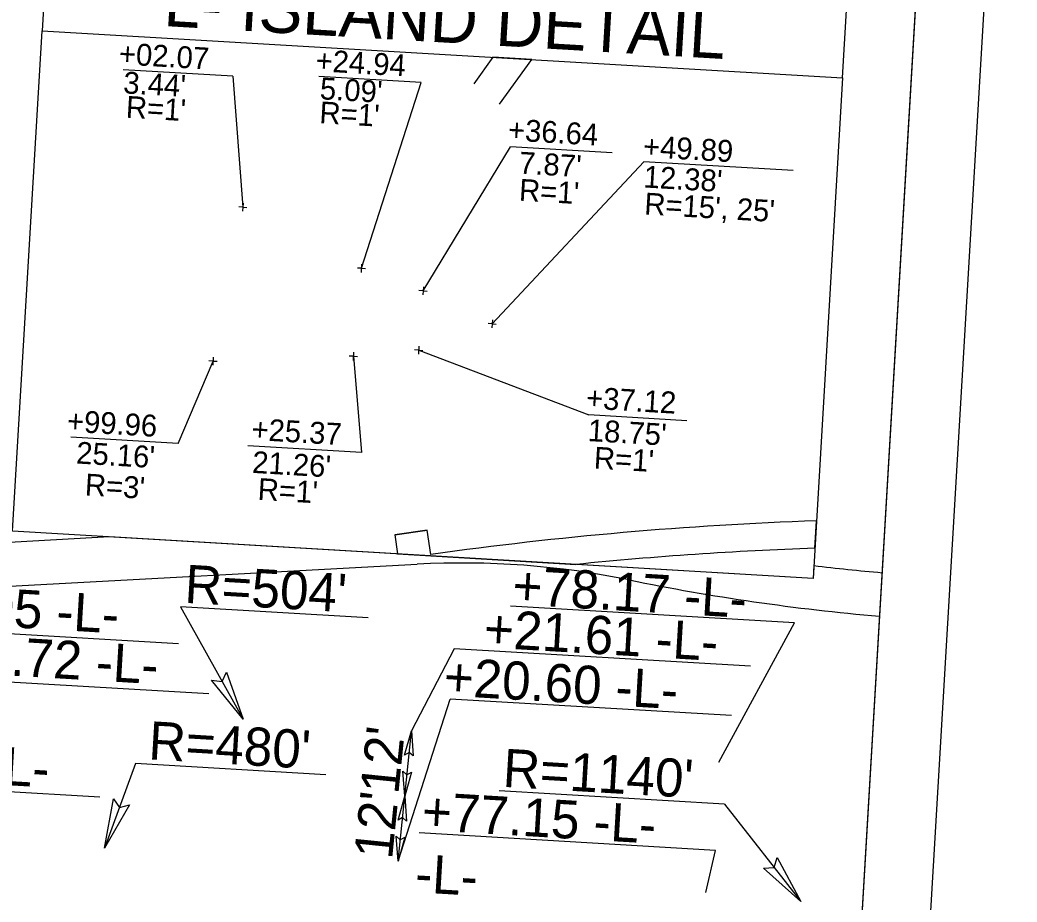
# Model space of a CAD drawing. Extents: x 2011491 to 2012372, y 444688 to 445287.
# Drawn here: x 2012189.4 to 2012371.9, y 444971.3 to 445132.9 of the extents above; entities that cross this region are included whole.
import ezdxf

# ---------------------------------------------------------------- set-up
doc = ezdxf.new("R2010")
doc.units = 0
for name, color, linetype in [('Old_Level_1', 7, 'Continuous'), ('Old_Level_10', 7, 'Continuous'), ('Prop Dimension', 7, 'Continuous'), ('Prop Dimension Text', 7, 'Continuous'), ('Prop Shade Medium', 7, 'Continuous'), ('Prop Terminator CELL', 7, 'Continuous'), ('Sheet Clip Boundary CELL', 7, 'Continuous'), ('Sheet Plan And Profile CELL', 7, 'Continuous'), ('Sheet Plot Border Outside CELL', 7, 'Continuous')]:
    doc.layers.add(name, color=color, linetype=linetype)

msp = doc.modelspace()

# ---------------------------------------------------------------- linework, layer by layer
at = {"layer": 'Old_Level_1'}
for points in [[(2012193.42, 445130.88), (2012339.99, 445122.24), (2012340.72, 445134.62), (2012194.15, 445143.26)], [(2012193.42, 445130.88), (2012339.99, 445122.24), (2012334.58, 445030.55), (2012188.02, 445039.19)]]:
    msp.add_lwpolyline(points, close=True, dxfattribs=at)
at = {"layer": 'Prop Dimension'}
for p, q in [((2012228.36, 445122.53), (2012208.27, 445123.71)), ((2012228.36, 445122.53), (2012230.18, 445098.55)), ((2012262.81, 445121.37), (2012244.08, 445122.47)), ((2012251.89, 445087.36), (2012262.81, 445121.37)), ((2012263.18, 445083.22), (2012279.17, 445109.62)), ((2012297.79, 445108.52), (2012279.17, 445109.62)), ((2012275.82, 445077.19), (2012303.59, 445106.89)), ((2012330.95, 445105.28), (2012303.59, 445106.89)), ((2012250.41, 445071.24), (2012251.91, 445053.59)), ((2012262.38, 445072.36), (2012293.55, 445060.5)), ((2012218.32, 445055.26), (2012224.73, 445070.36)), ((2012311.49, 445059.44), (2012293.55, 445060.5)), ((2012218.32, 445055.26), (2012198.66, 445056.42)), ((2012251.91, 445053.59), (2012231.1, 445054.82)), ((2012253.14, 445023.34), (2012218.75, 445025.36)), ((2012218.75, 445025.36), (2012230.22, 445004.78)), ((2012331.17, 445022.41), (2012279.21, 445025.47)), ((2012218.4, 445018.58), (2012165.6, 445021.69)), ((2012268.88, 445017.68), (2012261.03, 445002.6)), ((2012323.13, 445014.48), (2012268.88, 445017.68)), ((2012223.95, 445009.38), (2012170.99, 445012.51)), ((2012258.6, 444978.73), (2012268.16, 445008.46)), ((2012319.64, 445005.42), (2012268.16, 445008.46)), ((2012259.81, 444990.66), (2012261.03, 445002.6)), ((2012210.53, 444996.63), (2012204.86, 444981.15)), ((2012245.35, 444994.57), (2012210.53, 444996.63)), ((2012203.99, 444990.45), (2012150.17, 444993.62)), ((2012258.6, 444978.73), (2012259.81, 444990.66)), ((2012318.35, 444989.22), (2012277.13, 444991.65)), ((2012318.35, 444989.22), (2012332.37, 444971.37)), ((2012316.71, 444980.72), (2012262.46, 444983.92)), ((2012314.92, 444973.01), (2012316.71, 444980.72))]:
    msp.add_line(p, q, dxfattribs=at)
at = {"layer": 'Prop Dimension Text'}
for p, q in [((2012230.18, 445098.55), (2012229.44, 445098.59)), ((2012230.23, 445099.3), (2012230.14, 445097.8)), ((2012230.18, 445098.55), (2012230.93, 445098.5)), ((2012251.89, 445087.36), (2012251.14, 445087.4)), ((2012251.93, 445088.11), (2012251.84, 445086.61)), ((2012251.89, 445087.36), (2012252.64, 445087.32)), ((2012263.23, 445083.97), (2012263.14, 445082.47)), ((2012263.18, 445083.22), (2012262.43, 445083.27)), ((2012263.18, 445083.22), (2012263.93, 445083.18)), ((2012275.82, 445077.19), (2012275.07, 445077.23)), ((2012275.86, 445077.93), (2012275.77, 445076.44)), ((2012275.82, 445077.19), (2012276.56, 445077.14)), ((2012262.42, 445073.11), (2012262.34, 445071.61)), ((2012224.77, 445071.11), (2012224.68, 445069.61)), ((2012250.41, 445071.24), (2012249.66, 445071.29)), ((2012250.46, 445071.99), (2012250.37, 445070.5)), ((2012250.41, 445071.24), (2012251.16, 445071.2)), ((2012262.38, 445072.36), (2012261.63, 445072.4)), ((2012262.38, 445072.36), (2012263.13, 445072.31)), ((2012224.73, 445070.36), (2012223.98, 445070.41)), ((2012224.73, 445070.36), (2012225.48, 445070.32)), ((2012317.34, 444996.89), (2012331.17, 445022.41))]:
    msp.add_line(p, q, dxfattribs=at)
at = {"layer": 'Prop Shade Medium'}
for p, q in [((2012275.98, 445126.01), (2012272.47, 445121.18)), ((2012283.09, 445125.6), (2012275.98, 445126.01)), ((2012277.15, 445117.42), (2012283.09, 445125.6)), ((2012334.91, 445036.09), (2012335.2, 445041.11)), ((2012205.79, 445038.14), (2012139.27, 445034.57)), ((2012334.58, 445030.55), (2012205.79, 445038.14)), ((2012257.99, 445038.54), (2012263.93, 445039.4)), ((2012263.93, 445039.4), (2012257.99, 445038.54)), ((2012257.99, 445038.54), (2012258.5, 445035.03)), ((2012264.57, 445034.94), (2012263.93, 445039.4)), ((2012258.5, 445035.03), (2012291.16, 445033.11)), ((2012139.7, 445026.59), (2012262.08, 445033.14)), ((2012334.72, 445032.9), (2012334.58, 445030.55))]:
    msp.add_line(p, q, dxfattribs=at)
for centre, radius, start, end in [((2012359.25, 444358.03), 683.5, 92.01623, 97.96234), ((2012359.25, 444358.03), 678.5, 92.05607, 95.75966), ((2012270.28, 444880.14), 153.23, 78.456, 93.0671), ((2012381.79, 445426.09), 396, 263.1732, 264.99), ((2012381.79, 445426.09), 404, 258.456, 265.0224)]:
    msp.add_arc(centre, radius, start, end, dxfattribs=at)
at = {"layer": 'Prop Terminator CELL'}
for points in [[(2012227.2, 445013.39), (2012230.22, 445004.78), (2012224.42, 445011.91), (2012226.38, 445011.68)], [(2012259.8, 444998.2), (2012261.03, 445002.6), (2012261.36, 444998.02), (2012260.63, 444998.67)], [(2012261.04, 444995.06), (2012259.81, 444990.66), (2012259.47, 444995.25), (2012260.21, 444994.59)], [(2012258.59, 444986.27), (2012259.81, 444990.66), (2012260.15, 444986.08), (2012259.41, 444986.73)], [(2012209.41, 444989.07), (2012204.86, 444981.15), (2012206.47, 444990.2), (2012207.58, 444988.57)], [(2012259.83, 444983.12), (2012258.6, 444978.73), (2012258.26, 444983.31), (2012259, 444982.66)], [(2012328.03, 444979.41), (2012332.37, 444971.37), (2012325.52, 444977.5), (2012327.49, 444977.59)]]:
    msp.add_lwpolyline(points, close=True, dxfattribs=at)
at = {"layer": 'Sheet Clip Boundary CELL'}
for points in [[(2012353.36, 445134.84), (2012253.51, 445140.73), (2012256.91, 445198.29), (2012157.05, 445204.18), (2012159.02, 445237.47), (2011610.02, 445269.83), (2011579.13, 444745.74), (2012327.83, 444701.6)], [(2011579.79, 444746.22), (2011610.64, 445269.52), (2012158.83, 445237.2), (2012156.87, 445204), (2012256.73, 445198.11), (2012253.34, 445140.51), (2012353.28, 445134.62), (2012327.76, 444701.71)]]:
    msp.add_lwpolyline(points, close=True, dxfattribs=at)
at = {"layer": 'Sheet Plan And Profile CELL'}
msp.add_lwpolyline([(2012358.72, 445225.69), (2011610.02, 445269.83), (2011579.13, 444745.74), (2012327.83, 444701.6)], close=True, dxfattribs=at)
at = {"layer": 'Sheet Plot Border Outside CELL'}
msp.add_lwpolyline([(2011491.04, 444738.41), (2012339.57, 444688.39), (2012371.93, 445237.44), (2011523.41, 445287.46)], close=True, dxfattribs=at)

# ---------------------------------------------------------------- texts
at = {"layer": 'Old_Level_10'}
for s, p in [('+02.07', (2012207.4, 445124.74)), ('+24.94', (2012243.41, 445123.49)), ("3.44'", (2012208.21, 445119.42)), ("5.09'", (2012244.2, 445118.34)), ("R=1'", (2012208.68, 445114.96)), ("R=1'", (2012244.12, 445113.95)), ('+36.64', (2012278.64, 445110.8)), ('+49.89', (2012303.36, 445107.76)), ("7.87'", (2012280.66, 445104.73)), ("12.38'", (2012303.47, 445102.18)), ("R=1'", (2012280.67, 445099.76)), ("R=15', 25'", (2012303.61, 445097.24)), ('+37.12', (2012292.93, 445061.69)), ('+99.96', (2012197.89, 445057.45)), ('+25.37', (2012231.68, 445055.94)), ("18.75'", (2012293.26, 445055.72)), ("25.16'", (2012199.58, 445051.61)), ("R=1'", (2012294.37, 445050.69)), ("21.26'", (2012231.81, 445049.89)), ("R=3'", (2012201.18, 445045.77)), ("R=1'", (2012232.82, 445044.95))]:
    msp.add_text(s, height=4, rotation=356.6264, dxfattribs=at).set_placement(p)
at = {"layer": 'Prop Dimension'}
for s, height, p in [('-L- ISLAND DETAIL', 9, (2012211.53, 445131.99)), ('-L-', 7, (2012261.59, 444973.07))]:
    msp.add_text(s, height=height, rotation=356.6264, dxfattribs=at).set_placement(p)
at = {"layer": 'Prop Dimension Text'}
for s, rotation, p in [("R=504'", 356.6264, (2012219.4, 445026.09)), ('+78.17 -L-', 356.6264, (2012279.39, 445025.83)), ('+04.05 -L-', 356.6264, (2012164.46, 445022.98)), ('+21.61 -L-', 356.6264, (2012274.17, 445017.94)), ('+13.72 -L-', 356.6264, (2012171.68, 445013.69)), ('+20.60 -L-', 356.6264, (2012266.82, 445009.12)), ("R=480'", 356.6264, (2012212.79, 444997.41)), ("12'", 84.2042, (2012258.64, 444990.88)), ('+17.85 -L-', 356.6264, (2012151.72, 444994.75)), ("R=1140'", 356.6264, (2012277.66, 444992.38)), ("12'", 84.2042, (2012257.49, 444978.95)), ('+77.15 -L-', 356.6264, (2012262.8, 444984.48))]:
    msp.add_text(s, height=7, rotation=rotation, dxfattribs=at).set_placement(p)

doc.saveas('drawing.dxf')
